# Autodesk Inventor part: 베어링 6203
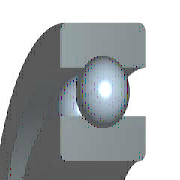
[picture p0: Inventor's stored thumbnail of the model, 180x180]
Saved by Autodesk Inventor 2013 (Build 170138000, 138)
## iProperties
IsCustomPart: 0
Company: 한국ATC센터
Created: 2014-10
Part Number: 베어링 6203
Material: 강철
Description: 깊은 그루브 볼 베어링
Document SubType Name: Modeling
Standard: KS B 2023
Designer: KYOUNG IL JANG
Standards Organization: KS
Language: ko-KR
Size Designation: 6203 - 17 x 40 x 12
Categories: <MemberInstance><Categories><Category DisplayName="샤프트 부품" InternalName="7f7aeb1f-a693-4053-b835-cee3144e0d98" Mnemonic="SHFT"><Category DisplayName="베어링" Inter
Density: 7.85 g/cm^3
Mass: 64.8982 g
Surface Area: 64.3582 cm^2
Volume: 8.26729 cm^3
Author: KYOUNG IL JANG
Revision Number: 1
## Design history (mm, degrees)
sketch "스케치" dims "d0" = 5.98 (= -0.26 x WD + 0.26 x BD)
  geometry: L1 (3.01, 14.25)-(8.99, 14.25); L2 (6, 14.25)-(6, 11.26); L3 (6, 14.25)-(6, 17.24); L4 (3.778, 12.249)-(0, 12.249); L5 (0, 8.5)-(12, 8.5); L6 (3.778, 16.251)-(0, 16.251); L7 (0, 20)-(12, 20); L8 (12, 8.5)-(12, 12.249); L9 (8.222, 12.249)-(12, 12.249); L10 (8.222, 16.251)-(12, 16.251); L11 (12, 20)-(12, 16.251); L12 (-1.4, 0)-(8.4, 0) reference; L13 (0, -0.3)-(0, 5.3) reference
  constraints: 22 end point, 4 point on line, 2 collinear, 2 perpendicular, 2 symmetric about line, 1 midpoint, 1 parallel, 14 other
  dimensions: "d9" = 17 diameter of L5 L12 (= WD); "d11" = 40 diameter of L7 L12 (= BD); "d12" = 12 distance between parallel lines of L8 L13 (= KB); "d13" = 24.498 diameter of L9 L12 (= 0.326 x BD + 0.674 x WD)
revolve "본체" stored, may be unused: angle "d6" = 90 deg
revolve "볼" stored, may be unused: angle "d7" = 90 deg
pattern_circular "IDS_ARRAYBALL[SIMPL:T]" dims angle "d3" = 360 deg
body "Solid1"
fillet "모깎기1" dims "d1" = 0.6 (= KRS)
other parameters: "WD" = 17 [user parameter; used in 5 equation terms], "BD" = 40 [user parameter; used in 5 equation terms], "KB" = 12 [user parameter; used in 1 equation term], "KRS" = 0.6 [user parameter; used in 1 equation term], "d4" = 0, "d5" = 0, "d8" = 0, "d14" = 0, "d15" = 0, "BBA" = 0 [user parameter], "BC0" = 4750000 [user parameter], "BC" = 9560000 [user parameter], "WR" = 8.5 (= 0.5 x WD) [user parameter]
